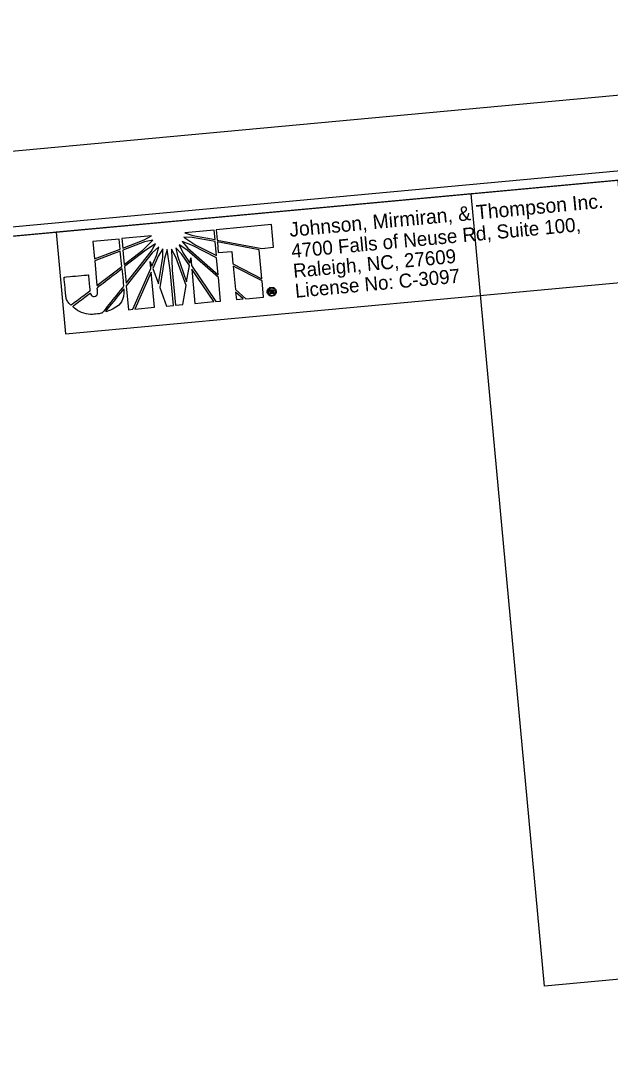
# Model space of a CAD drawing. Extents: x 1724152 to 1726026, y 971581 to 972827.
# Drawn here: x 1725455.7 to 1725612.3, y 972548.8 to 972826.6 of the extents above; entities that cross this region are included whole.
import ezdxf

# ---------------------------------------------------------------- set-up
doc = ezdxf.new("R2010")
doc.units = 0
for name, color, linetype in [('Prop Dimension Text', 7, 'Continuous'), ('Sheet Clip Boundary CELL', 7, 'Continuous'), ('Sheet Layout Plan Border', 7, 'Continuous'), ('Sheet Plan CELL', 7, 'Continuous'), ('Sheet Plot Border Inside CELL', 7, 'Continuous'), ('Sheet Plot Border Outside CELL', 7, 'Continuous')]:
    doc.layers.add(name, color=color, linetype=linetype)

msp = doc.modelspace()

# ---------------------------------------------------------------- linework, layer by layer
at = {"layer": 'Prop Dimension Text'}
for p, q in [((1725507.03, 972770.99), (1725499.27, 972770.3)), ((1725499.27, 972770.3), (1725501.32, 972769.56)), ((1725507.26, 972768.47), (1725507.03, 972770.99)), ((1725522.26, 972772.45), (1725507.56, 972771.07)), ((1725507.56, 972771.07), (1725507.82, 972768.38)), ((1725522.82, 972766.43), (1725522.26, 972772.45)), ((1725481.77, 972768.63), (1725474.78, 972767.97)), ((1725474.78, 972767.97), (1725475.22, 972763.34)), ((1725482.03, 972765.93), (1725481.77, 972768.63)), ((1725490.37, 972769.47), (1725482.5, 972768.73)), ((1725482.5, 972768.73), (1725482.73, 972766.23)), ((1725482.73, 972766.23), (1725488.44, 972768.39)), ((1725488.49, 972767.85), (1725482.78, 972765.69)), ((1725488.07, 972765.71), (1725490.75, 972768.34)), ((1725488.44, 972768.39), (1725490.37, 972769.47)), ((1725490.75, 972768.34), (1725488.49, 972767.85)), ((1725491.43, 972767.31), (1725488.89, 972765.71)), ((1725490.26, 972765.29), (1725491.43, 972767.31)), ((1725497.74, 972767.05), (1725498.8, 972764.89)), ((1725499.73, 972765.79), (1725497.74, 972767.05)), ((1725498.48, 972767.97), (1725500.01, 972766.17)), ((1725501.3, 972766.87), (1725498.48, 972767.97)), ((1725498.99, 972769.11), (1725502.14, 972766.98)), ((1725501.17, 972769.03), (1725498.99, 972769.11)), ((1725507.31, 972767.94), (1725501.17, 972769.03)), ((1725501.32, 972769.56), (1725507.26, 972768.47)), ((1725502.14, 972766.98), (1725507.61, 972764.24)), ((1725507.61, 972764.24), (1725507.31, 972767.94)), ((1725507.82, 972768.38), (1725507.82, 972768.29)), ((1725507.82, 972768.29), (1725519.7, 972766.14)), ((1725507.86, 972767.88), (1725507.87, 972767.83)), ((1725518.98, 972765.8), (1725507.86, 972767.88)), ((1725507.87, 972767.83), (1725508.13, 972765.02)), ((1725475.22, 972763.34), (1725482.03, 972765.93)), ((1725482.07, 972765.42), (1725475.27, 972762.81)), ((1725482.45, 972761.37), (1725482.07, 972765.42)), ((1725482.78, 972765.69), (1725483.14, 972761.9)), ((1725483.14, 972761.9), (1725488.07, 972765.71)), ((1725488.89, 972765.71), (1725483.19, 972761.29)), ((1725483.6, 972756.93), (1725490.26, 972765.29)), ((1725490.59, 972764.94), (1725483.67, 972756.19)), ((1725490.45, 972761.42), (1725491.67, 972764.22)), ((1725492.31, 972766.54), (1725490.59, 972764.94)), ((1725491.67, 972764.22), (1725492.31, 972766.54)), ((1725493.38, 972766.01), (1725492.16, 972764.11)), ((1725493.38, 972763.84), (1725493.38, 972766.01)), ((1725494.56, 972765.81), (1725493.81, 972763.48)), ((1725495.37, 972760.32), (1725494.56, 972765.81)), ((1725495.71, 972765.92), (1725495.87, 972760.37)), ((1725496.84, 972763.77), (1725495.71, 972765.92)), ((1725496.8, 972766.33), (1725497.24, 972764.12)), ((1725498.32, 972764.68), (1725496.8, 972766.33)), ((1725500.44, 972761.58), (1725498.32, 972764.68)), ((1725498.8, 972764.89), (1725500.56, 972762.25)), ((1725508.16, 972758.41), (1725499.73, 972765.79)), ((1725500.01, 972766.17), (1725508.09, 972759.14)), ((1725507.67, 972763.61), (1725501.3, 972766.87)), ((1725508.13, 972765.02), (1725511.72, 972765.35)), ((1725511.72, 972765.35), (1725512.03, 972762)), ((1725519.71, 972758.08), (1725518.98, 972765.8)), ((1725519.7, 972766.14), (1725522.82, 972766.43)), ((1725475.27, 972762.81), (1725475.88, 972756.29)), ((1725490.16, 972760.81), (1725489.99, 972762.66)), ((1725489.99, 972762.66), (1725490.45, 972761.42)), ((1725492.16, 972764.11), (1725490.71, 972760.78)), ((1725492.22, 972756.69), (1725493.38, 972763.84)), ((1725493.81, 972763.48), (1725492.54, 972755.74)), ((1725499.57, 972756.28), (1725496.84, 972763.77)), ((1725497.24, 972764.12), (1725499.71, 972757.23)), ((1725499.71, 972757.23), (1725500.44, 972761.58)), ((1725500.56, 972762.25), (1725500.79, 972763.67)), ((1725500.79, 972763.67), (1725500.98, 972761.63)), ((1725500.98, 972761.63), (1725507.51, 972752.02)), ((1725508.09, 972759.14), (1725507.67, 972763.61)), ((1725512.03, 972762), (1725519.71, 972758.08)), ((1725512.09, 972761.42), (1725512.67, 972755.17)), ((1725519.76, 972757.54), (1725512.09, 972761.42)), ((1725475.88, 972756.29), (1725482.45, 972761.37)), ((1725483.19, 972761.29), (1725483.6, 972756.93)), ((1725485.42, 972749.96), (1725490.16, 972760.81)), ((1725490.26, 972759.81), (1725485.96, 972750.01)), ((1725491.17, 972750.49), (1725490.26, 972759.81)), ((1725490.71, 972760.78), (1725492.22, 972756.69)), ((1725496.25, 972751), (1725495.37, 972760.32)), ((1725495.87, 972760.37), (1725496.74, 972751.05)), ((1725506.93, 972752), (1725501.07, 972760.62)), ((1725501.07, 972760.62), (1725501.92, 972751.53)), ((1725483.67, 972756.19), (1725484.26, 972749.85)), ((1725498.68, 972751.23), (1725499.57, 972756.28)), ((1725508.74, 972752.14), (1725508.16, 972758.41)), ((1725520.16, 972753.2), (1725519.76, 972757.54)), ((1725492.54, 972755.74), (1725494.33, 972750.82)), ((1725512.67, 972755.17), (1725515.42, 972752.76)), ((1725514.73, 972752.7), (1725512.73, 972754.49)), ((1725512.73, 972754.49), (1725512.92, 972752.53)), ((1725515.42, 972752.76), (1725520.16, 972753.2)), ((1725521.84, 972755.11), (1725522.28, 972755.15)), ((1725521.94, 972754.04), (1725521.84, 972755.11)), ((1725522.18, 972754.06), (1725521.94, 972754.04)), ((1725522.3, 972754.94), (1725522.1, 972754.92)), ((1725522.1, 972754.92), (1725522.13, 972754.67)), ((1725522.13, 972754.67), (1725522.32, 972754.69)), ((1725522.34, 972754.49), (1725522.14, 972754.48)), ((1725522.14, 972754.48), (1725522.18, 972754.06)), ((1725522.22, 972755.78), (1725522.24, 972755.55)), ((1725522.24, 972755.55), (1725522.22, 972755.78)), ((1725522.28, 972755.15), (1725522.3, 972754.94)), ((1725522.3, 972754.94), (1725522.28, 972755.15)), ((1725522.28, 972755.15), (1725522.35, 972755.15)), ((1725522.33, 972754.94), (1725522.3, 972754.94)), ((1725522.32, 972754.69), (1725522.34, 972754.49)), ((1725522.34, 972754.49), (1725522.32, 972754.69)), ((1725522.32, 972754.69), (1725522.33, 972754.69)), ((1725522.35, 972754.5), (1725522.34, 972754.49)), ((1725522.42, 972753.66), (1725522.44, 972753.43)), ((1725522.44, 972753.43), (1725522.42, 972753.66)), ((1725522.42, 972753.66), (1725522.43, 972753.66)), ((1725522.45, 972753.43), (1725522.44, 972753.43)), ((1725485.96, 972750.01), (1725491.17, 972750.49)), ((1725494.33, 972750.82), (1725496.25, 972751)), ((1725496.74, 972751.05), (1725498.68, 972751.23)), ((1725501.92, 972751.53), (1725506.93, 972752)), ((1725507.51, 972752.02), (1725508.74, 972752.14)), ((1725512.92, 972752.53), (1725514.73, 972752.7)), ((1725484.26, 972749.85), (1725485.42, 972749.96))]:
    msp.add_line(p, q, dxfattribs=at)
msp.add_lwpolyline([(1725467.52, 972743.45), (1725616.91, 972757.28), (1725614.41, 972784.23), (1725465.02, 972770.41)], close=True, dxfattribs=at)
for points in [[(1725501.32, 972769.56), (1725507.26, 972768.47), (1725507.03, 972770.99), (1725499.27, 972770.3), (1725501.32, 972769.56)], [(1725522.26, 972772.45), (1725507.56, 972771.07), (1725507.82, 972768.38), (1725507.82, 972768.29), (1725519.7, 972766.14), (1725522.82, 972766.43), (1725522.26, 972772.45)], [(1725475.22, 972763.34), (1725482.03, 972765.93), (1725481.77, 972768.63), (1725474.78, 972767.97), (1725475.22, 972763.34)], [(1725488.44, 972768.39), (1725490.37, 972769.47), (1725482.5, 972768.73), (1725482.73, 972766.23), (1725488.44, 972768.39)], [(1725482.78, 972765.69), (1725483.14, 972761.9), (1725488.07, 972765.71), (1725490.75, 972768.34), (1725488.49, 972767.85), (1725482.78, 972765.69)], [(1725483.19, 972761.29), (1725483.6, 972756.93), (1725490.26, 972765.29), (1725491.43, 972767.31), (1725488.89, 972765.71), (1725483.19, 972761.29)], [(1725497.74, 972767.05), (1725498.8, 972764.89), (1725500.56, 972762.25), (1725500.79, 972763.67), (1725500.98, 972761.63), (1725507.51, 972752.02), (1725508.74, 972752.14), (1725508.16, 972758.41), (1725499.73, 972765.79), (1725497.74, 972767.05)], [(1725498.48, 972767.97), (1725500.01, 972766.17), (1725508.09, 972759.14), (1725507.67, 972763.61), (1725501.3, 972766.87), (1725498.48, 972767.97)], [(1725498.99, 972769.11), (1725502.14, 972766.98), (1725507.61, 972764.24), (1725507.31, 972767.94), (1725501.17, 972769.03), (1725498.99, 972769.11)], [(1725507.86, 972767.88), (1725507.87, 972767.83), (1725508.13, 972765.02), (1725511.72, 972765.35), (1725512.03, 972762), (1725519.71, 972758.08), (1725518.98, 972765.8), (1725507.86, 972767.88)], [(1725475.88, 972756.29), (1725482.45, 972761.37), (1725482.07, 972765.42), (1725475.27, 972762.81), (1725475.88, 972756.29)], [(1725492.31, 972766.54), (1725490.59, 972764.94), (1725483.67, 972756.19), (1725484.26, 972749.85), (1725485.42, 972749.96), (1725490.16, 972760.81), (1725489.99, 972762.66), (1725490.45, 972761.42), (1725491.67, 972764.22), (1725492.31, 972766.54)], [(1725493.38, 972766.01), (1725492.16, 972764.11), (1725490.71, 972760.78), (1725492.22, 972756.69), (1725493.38, 972763.84), (1725493.38, 972766.01)], [(1725493.81, 972763.48), (1725492.54, 972755.74), (1725494.33, 972750.82), (1725496.25, 972751), (1725495.37, 972760.32), (1725494.56, 972765.81), (1725493.81, 972763.48)], [(1725495.71, 972765.92), (1725495.87, 972760.37), (1725496.74, 972751.05), (1725498.68, 972751.23), (1725499.57, 972756.28), (1725496.84, 972763.77), (1725495.71, 972765.92)], [(1725496.8, 972766.33), (1725497.24, 972764.12), (1725499.71, 972757.23), (1725500.44, 972761.58), (1725498.32, 972764.68), (1725496.8, 972766.33)], [(1725512.09, 972761.42), (1725512.67, 972755.17), (1725515.42, 972752.76), (1725520.16, 972753.2), (1725519.76, 972757.54), (1725512.09, 972761.42), (1725512.09, 972761.42)], [(1725485.96, 972750.01), (1725491.17, 972750.49), (1725490.26, 972759.81), (1725485.96, 972750.01)], [(1725501.92, 972751.53), (1725506.93, 972752), (1725501.07, 972760.62), (1725501.92, 972751.53)], [(1725512.92, 972752.53), (1725512.92, 972752.53), (1725514.73, 972752.7), (1725512.73, 972754.49), (1725512.92, 972752.53)], [(1725522.82, 972754.37), (1725522.83, 972754.32), (1725522.84, 972754.28), (1725522.84, 972754.24), (1725522.88, 972754.12), (1725522.66, 972754.1)]]:
    msp.add_lwpolyline(points, dxfattribs=at)
for points, degree in [([(1725473.59, 972759.1), (1725473.59, 972759.1), (1725467.12, 972758.5), (1725467.12, 972758.5), (1725467.12, 972758.5), (1725467.5, 972754.45), (1725467.5, 972754.45), (1725467.5, 972754.45), (1725467.54, 972754.02), (1725467.54, 972754.02), (1725467.66, 972752.75), (1725468.16, 972751.79), (1725468.98, 972751.01), (1725468.98, 972751.01), (1725474, 972754.74), (1725473.99, 972754.82), (1725473.99, 972754.82), (1725473.59, 972759.1), (1725473.59, 972759.1)], 3), ([(1725475.14, 972753.37), (1725474.72, 972753.33), (1725474.34, 972753.53), (1725474.12, 972754.29), (1725474.12, 972754.29), (1725469.39, 972750.71), (1725469.39, 972750.71), (1725471.09, 972749.23), (1725473.65, 972748.49), (1725475.74, 972748.69), (1725476.28, 972748.74), (1725476.69, 972748.82), (1725477.26, 972748.99), (1725477.26, 972748.99), (1725482.95, 972756.09), (1725482.95, 972756.09), (1725482.95, 972756.09), (1725482.51, 972760.8), (1725482.51, 972760.8), (1725482.51, 972760.8), (1725475.93, 972755.7), (1725475.93, 972755.7), (1725476.1, 972753.94), (1725475.71, 972753.42), (1725475.14, 972753.37)], 3), ([(1725475.14, 972753.37), (1725474.72, 972753.33), (1725474.34, 972753.53), (1725474.12, 972754.29), (1725474.12, 972754.29), (1725469.39, 972750.71), (1725469.39, 972750.71), (1725471.09, 972749.23), (1725473.65, 972748.49), (1725475.74, 972748.69), (1725476.28, 972748.74), (1725476.69, 972748.82), (1725477.26, 972748.99), (1725477.26, 972748.99), (1725482.95, 972756.09), (1725482.95, 972756.09), (1725482.95, 972756.09), (1725482.51, 972760.8), (1725482.51, 972760.8), (1725482.51, 972760.8), (1725475.93, 972755.7), (1725475.93, 972755.7), (1725476.1, 972753.94), (1725475.71, 972753.42), (1725475.14, 972753.37)], 3), ([(1725483.02, 972755.35), (1725483.02, 972755.35), (1725478.1, 972749.22), (1725478.1, 972749.22), (1725480.7, 972750.13), (1725483.19, 972752.14), (1725483.02, 972755.35)], 3), ([(1725522.44, 972753.43), (1725522.12, 972753.4), (1725521.83, 972753.49), (1725521.57, 972753.7), (1725521.32, 972753.9), (1725521.17, 972754.17), (1725521.14, 972754.5), (1725521.11, 972754.83), (1725521.2, 972755.12), (1725521.42, 972755.36), (1725521.63, 972755.6), (1725521.89, 972755.75), (1725522.22, 972755.78)], 3), ([(1725522.24, 972755.55), (1725521.98, 972755.53), (1725521.76, 972755.42), (1725521.59, 972755.23), (1725521.43, 972755.03), (1725521.35, 972754.78), (1725521.38, 972754.52), (1725521.4, 972754.26), (1725521.52, 972754.04), (1725521.72, 972753.87), (1725521.92, 972753.7), (1725522.16, 972753.64), (1725522.42, 972753.66)], 3), ([(1725522.22, 972755.78), (1725522.55, 972755.81), (1725522.84, 972755.72), (1725523.1, 972755.52), (1725523.35, 972755.32), (1725523.49, 972755.05), (1725523.52, 972754.72)], 3), ([(1725522.43, 972753.66), (1725522.69, 972753.69), (1725522.9, 972753.79), (1725523.07, 972754), (1725523.24, 972754.2), (1725523.31, 972754.44), (1725523.29, 972754.7), (1725523.27, 972754.96), (1725523.15, 972755.19), (1725522.94, 972755.36), (1725522.74, 972755.51), (1725522.51, 972755.58), (1725522.24, 972755.55)], 3), ([(1725522.33, 972754.69), (1725522.49, 972754.7), (1725522.56, 972754.76), (1725522.55, 972754.85), (1725522.54, 972754.93), (1725522.47, 972754.96), (1725522.33, 972754.94)], 3), ([(1725522.35, 972755.15), (1725522.62, 972755.18), (1725522.76, 972755.08), (1725522.78, 972754.87), (1725522.79, 972754.77), (1725522.76, 972754.69), (1725522.68, 972754.62)], 3), ([(1725522.54, 972754.47), (1725522.51, 972754.49), (1725522.45, 972754.5), (1725522.35, 972754.5)], 2), ([(1725523.52, 972754.72), (1725523.55, 972754.39), (1725523.46, 972754.1), (1725523.26, 972753.85), (1725523.05, 972753.6), (1725522.78, 972753.46), (1725522.45, 972753.43)], 3), ([(1725522.66, 972754.1), (1725522.63, 972754.16), (1725522.6, 972754.22), (1725522.59, 972754.29), (1725522.58, 972754.39), (1725522.57, 972754.45), (1725522.54, 972754.47)], 3), ([(1725522.68, 972754.62), (1725522.75, 972754.59), (1725522.8, 972754.51), (1725522.82, 972754.37)], 2)]:
    msp.add_open_spline(points, degree=degree, dxfattribs=at)
at = {"layer": 'Sheet Clip Boundary CELL'}
msp.add_lwpolyline([(1724466.5, 971623.53), (1725860.56, 971752.51), (1725783.31, 972587.46), (1725594.85, 972570.02), (1725575.37, 972780.61), (1724369.77, 972669.06)], close=True, dxfattribs=at)
at = {"layer": 'Sheet Layout Plan Border'}
msp.add_lwpolyline([(1725733.83, 972795.27), (1725723.88, 972794.35), (1724369.77, 972669.06), (1724487.01, 971625.42), (1724638.15, 971639.41), (1724679.57, 971643.24), (1725830.66, 971749.75)], close=True, dxfattribs=at)
at = {"layer": 'Sheet Plan CELL'}
msp.add_lwpolyline([(1725813.64, 972802.65), (1724319.98, 972664.46), (1724416.72, 971618.92), (1725910.35, 971757.12)], close=True, dxfattribs=at)
at = {"layer": 'Sheet Plot Border Inside CELL'}
msp.add_lwpolyline([(1724264.11, 971602.28), (1725923.01, 971755.78), (1725825.83, 972806.28), (1724166.92, 972652.79)], close=True, dxfattribs=at)
at = {"layer": 'Sheet Plot Border Outside CELL'}
msp.add_lwpolyline([(1724253.01, 971581.17), (1725929.35, 971736.27), (1725828.47, 972826.61), (1724152.13, 972671.51)], close=True, dxfattribs=at)

# ---------------------------------------------------------------- texts
at = {"layer": 'Prop Dimension Text'}
for s, height, p in [('Johnson, Mirmiran, & Thompson Inc.', 3.8334, (1725527.18, 972769.2)), ('4700 Falls of Neuse Rd, Suite 100, ', 3.7239, (1725527.7, 972763.6)), ('Raleigh, NC, 27609', 3.7239, (1725528.19, 972758.3)), ('License No: C-3097', 3.7239, (1725528.68, 972753))]:
    msp.add_text(s, height=height, rotation=5.2878, dxfattribs=at).set_placement(p)

doc.saveas('drawing.dxf')
